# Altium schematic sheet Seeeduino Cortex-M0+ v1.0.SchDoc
size 545 x 376 mm; Origin: Eagle
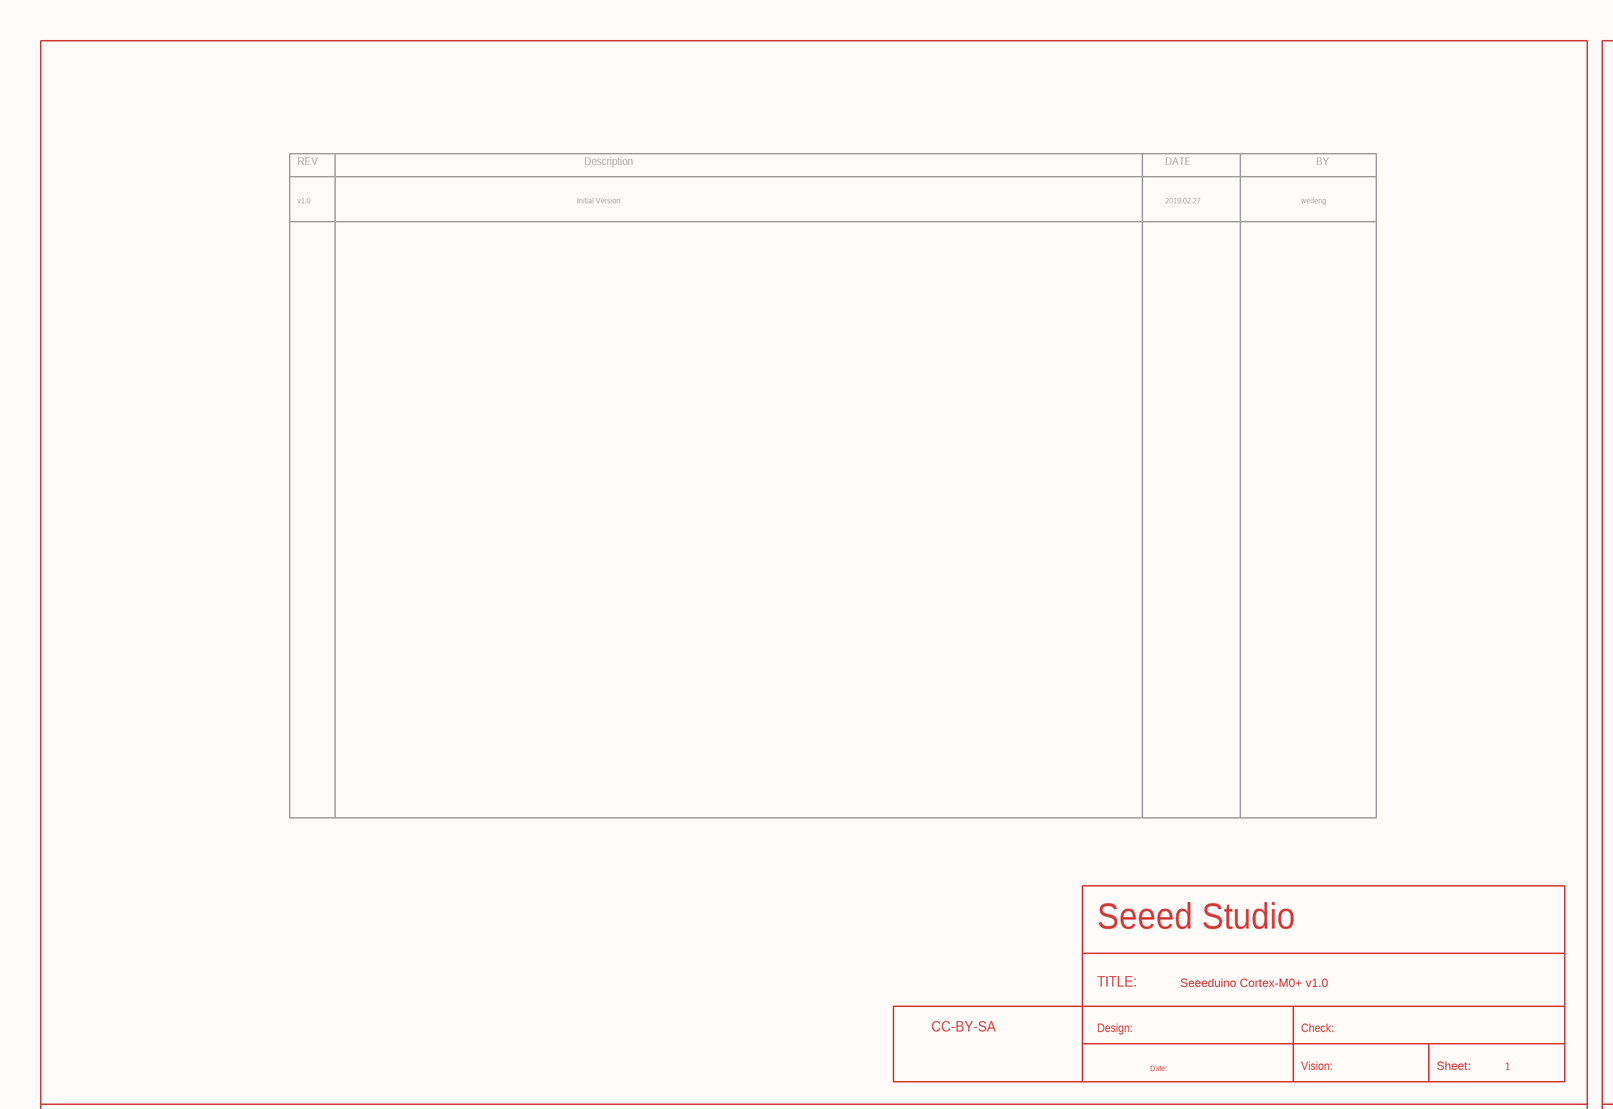
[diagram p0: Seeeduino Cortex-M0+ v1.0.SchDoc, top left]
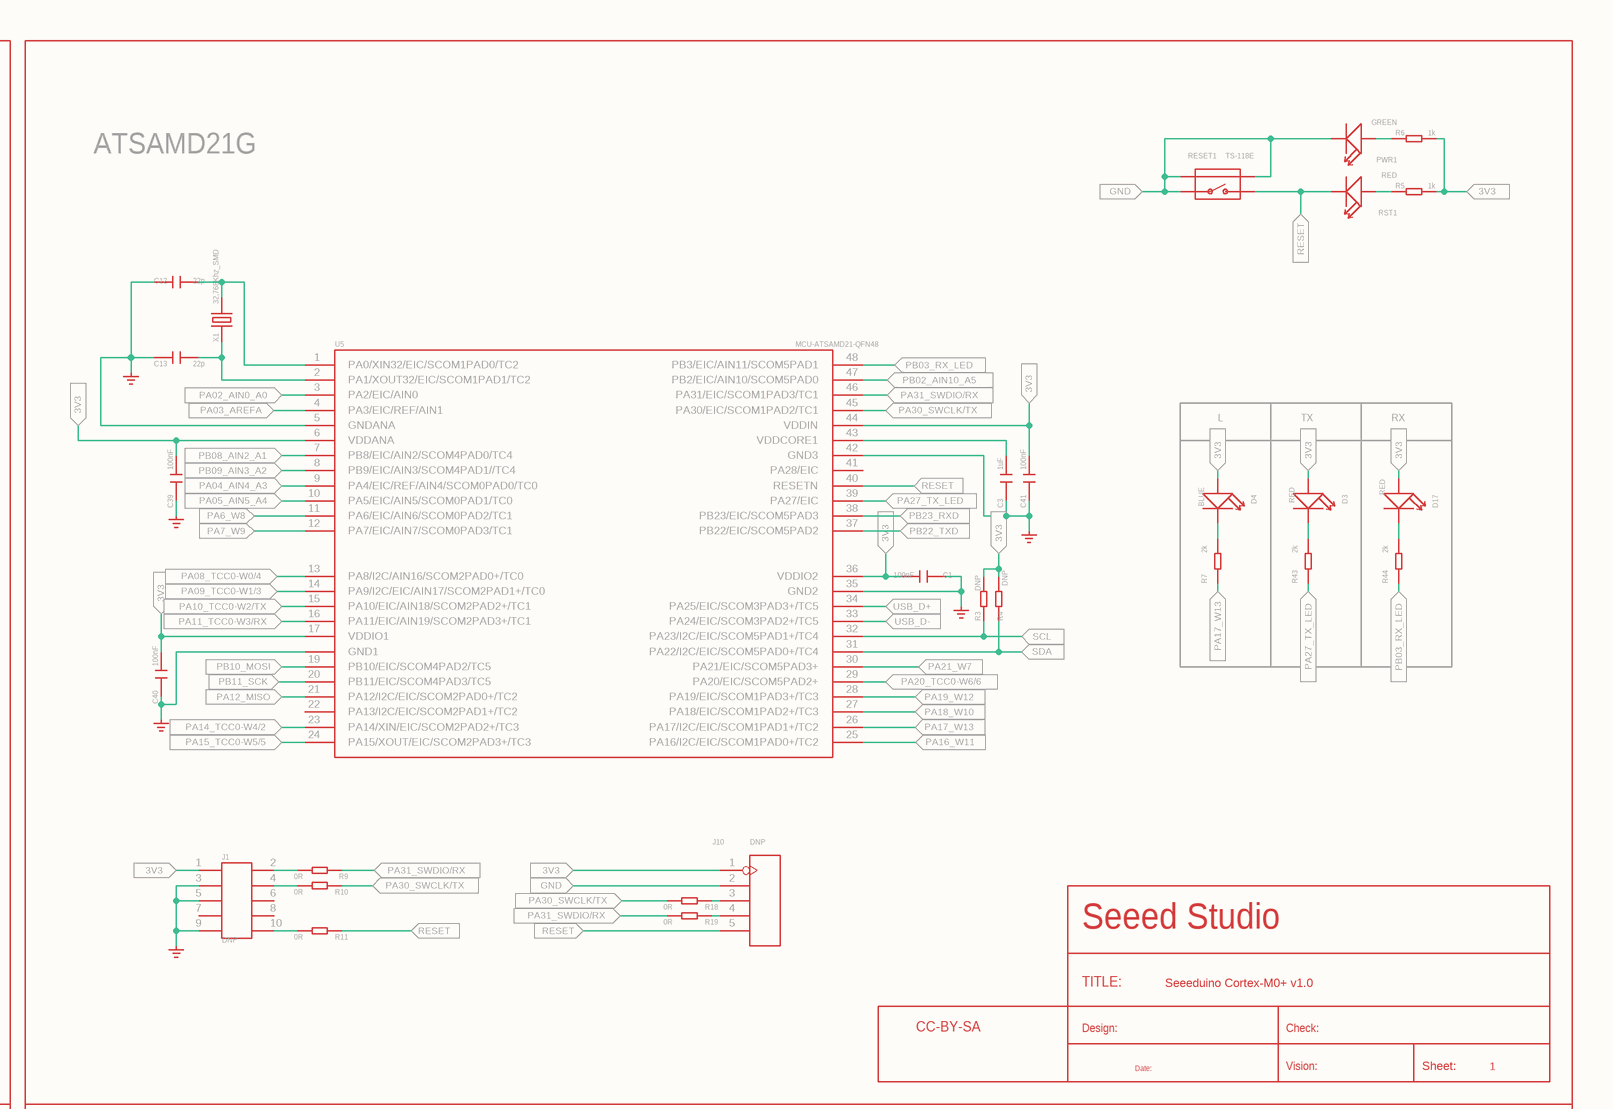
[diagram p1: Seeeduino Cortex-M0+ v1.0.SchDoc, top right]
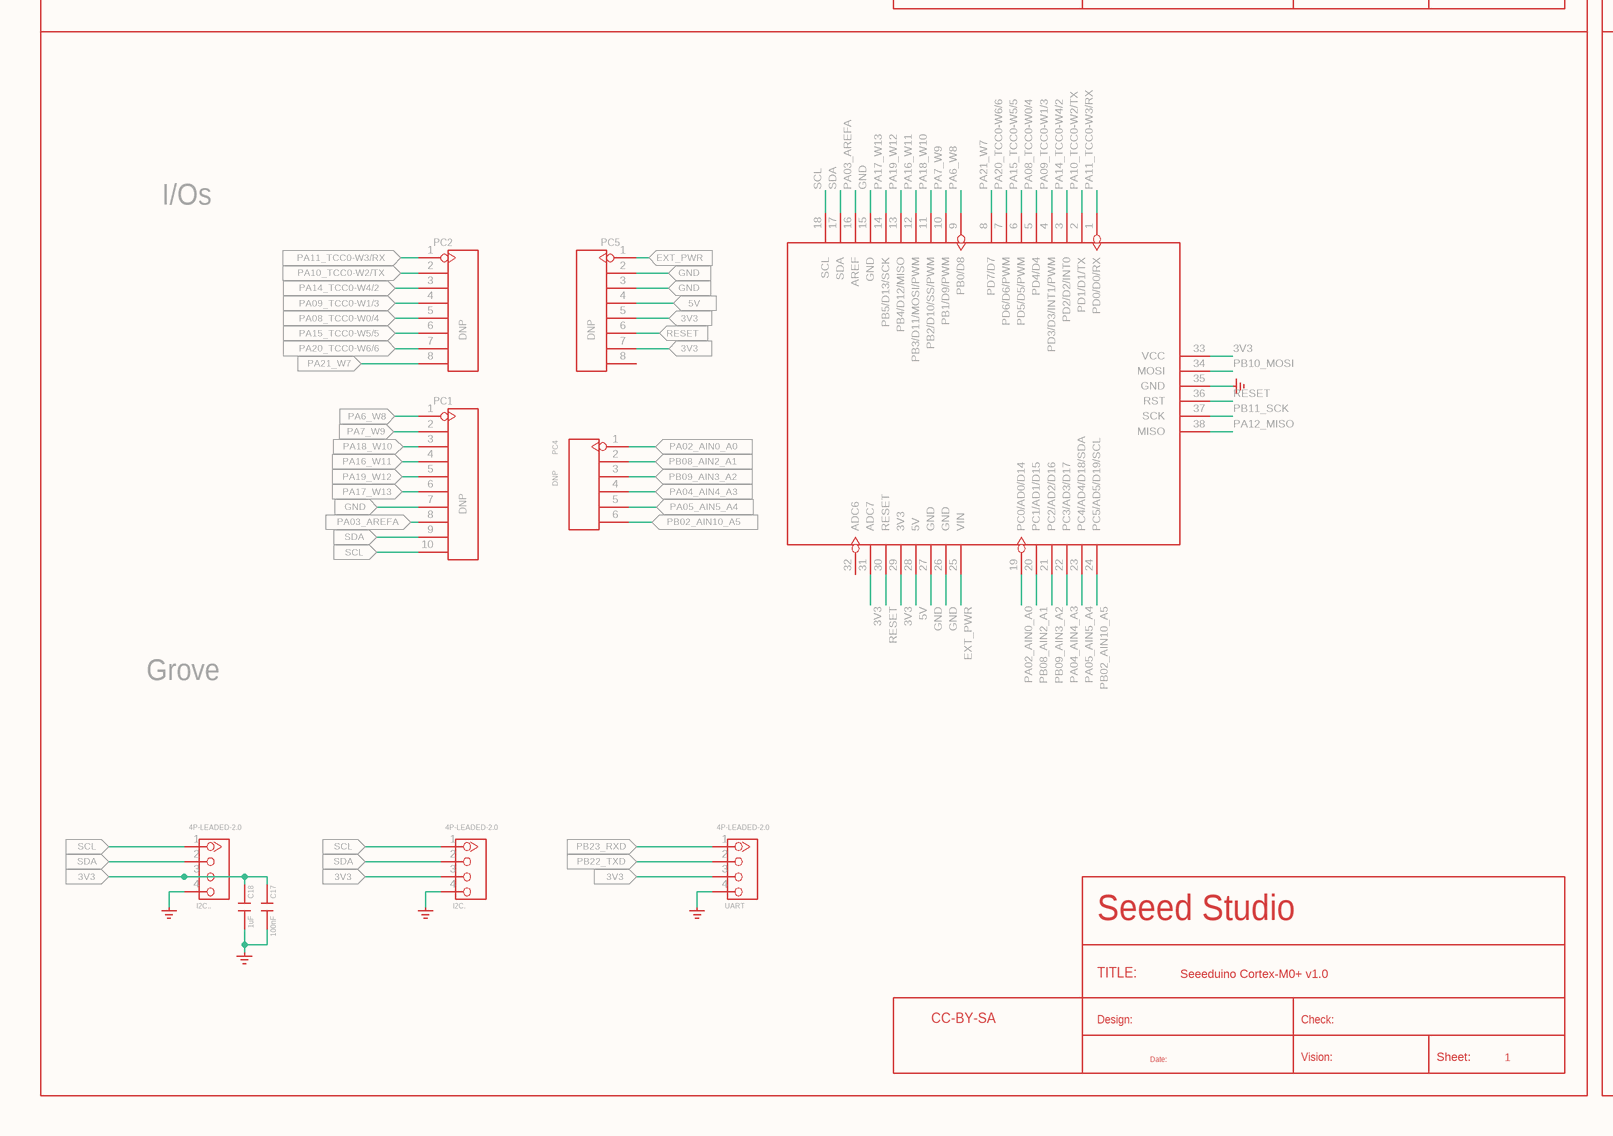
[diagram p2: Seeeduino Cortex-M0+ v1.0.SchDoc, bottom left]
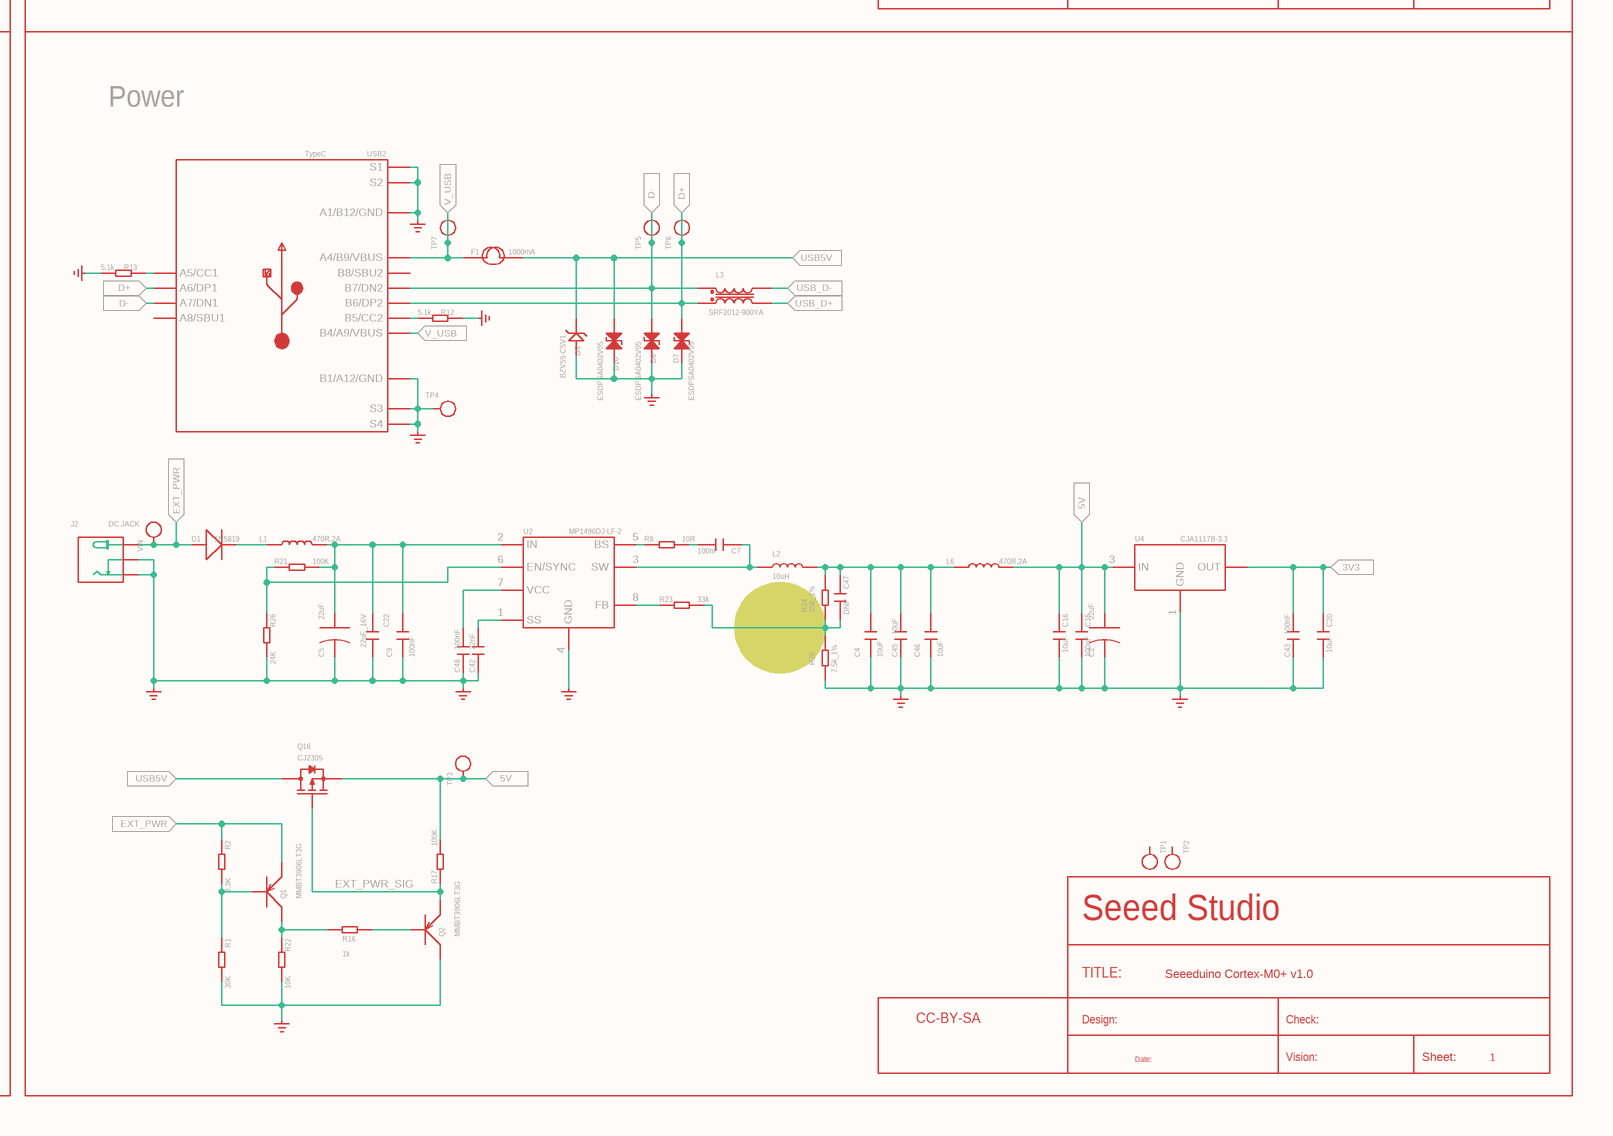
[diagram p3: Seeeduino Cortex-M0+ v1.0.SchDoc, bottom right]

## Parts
C1  100nF  [C0603]
C2  22uF  [ELECTRO-SMD-B-4.8MM]
C3  1uF  [C0603]
C4  10uF  [C0805]
C5  22uF  [ELECTRO-SMD-B-4.8MM]
C7  100nF  [C0603]
C9  100nF  [C0603]
C12  22p  [C0603]
C13  22p  [C0603]
C15  100nF  [C0603]
C16  10uF  [C0805]
C17  100nF  [C0603]
C18  1uF  [C0603]
C20  10uF  [C0805]
C22  22uF_16V  [C1206]
C39  100nF  [C0603]
C40  100nF  [C0603]
C41  100nF  [C0603]
C42  22nF  [C0603]
C43  100nF  [C0603]
C45  10uF  [C0805]
C46  10uF  [C0805]
C47  DNP  [C0603]
C48  100nF  [C0603]
D1  1N5819  [D2010]
D3  RED  [LED-0603]
D4  BLUE  [LED-0603]
D5  BZV55-C5V1  [SOD80C]
D6  ESDPSA0402V05  [ESD-0402]
D7  ESDPSA0402V05  [ESD-0402]
D10  ESDPSA0402V05  [ESD-0402]
D17  RED  [LED-0603]
F1  1000mA  [F1206]
I2C.  4P-LEADED-2.0  [4P-LEADED-2.0]
I2C..  4P-LEADED-2.0  [4P-LEADED-2.0]
J1  DNP  [H2X5-1.27]
J2  DC JACK  [DCJ3P-11.6X9.6X7.0MM]
J10  DNP  [H5-2.54]
L1  470R,2A  [L0805]
L2  10uH  [L5040S]
L3  SRF2012-900YA  [INT4-0.85-2X1.25X1.2MM]
L6  470R,2A  [L0805]
PC1  DNP  [10P-2.54]
PC2  DNP  [8P-2.54]
PC4  DNP  [6P-2.54-65/35MIL]
PC5  DNP  [8P-2.54]
PWR1  GREEN  [LED-0603]
Q1  MMBT3906LT3G  [SOT23]
Q2  MMBT3906LT3G  [SOT23]
Q16  CJ2305  [SOT23]
R1  30K  [R0603]
R2  3.3K  [R0603]
R3  DNP  [R0603]
R4  DNP  [R0603]
R5  1k  [R0603]
R6  1k  [R0603]
R7  2k  [R0603]
R8  10R  [R0603]
R9  0R  [R0603]
R10  0R  [R0603]
R11  0R  [R0603]
R12  5.1k  [R0603]
R13  5.1k  [R0603]
R16  1k  [R0603]
R17  100K  [R0603]
R18  0R  [R0603]
R19  0R  [R0603]
R20  7.5k_1%  [R0603]
R21  100K  [R0603]
R22  10K  [R0603]
R23  33k  [R0603]
R24  39k_1%  [R0603]
R26  24K  [R0603]
R43  2k  [R0603]
R44  2k  [R0603]
RESET1  TS-118E  [4P-SMD-7X3.5X3.5H]
RST1  RED  [LED-0603]
TP1  TEST-POINT'4545'  [TP-D45MIL]  (value not drawn)
TP2  TEST-POINT'4545'  [TP-D45MIL]  (value not drawn)
TP3  TEST-POINT'4545'  [TP-D45MIL]  (value not drawn)
TP4  TEST-POINT'4545'  [TP-D45MIL]  (value not drawn)
TP5  TEST-POINT'4545'  [TP-D45MIL]  (value not drawn)
TP6  TEST-POINT'4545'  [TP-D45MIL]  (value not drawn)
TP7  TEST-POINT'4545'  [TP-D45MIL]  (value not drawn)
U2  MP1496DJ-LF-2  [TSOT23-8]
U3  ARDUINO-38P  [ARDUINO-38P]  (value not drawn)
U4  CJA1117B-3.3  [SOT-89]
U5  MCU-ATSAMD21-QFN48  [QFN48-7X7]
U$1  DRAWING_NAME: Seeeduino Cortex-M0+ v1.0  SHEET: 1  Sheet: Sheet:  SeeedStudio: Seeed Studio  TITLE: TITLE:  Design: Design:  Check: Check:  Vision: Vision:  Date: Date:  [SEEEDSTUDIO-PCB-FRAME]  (hidden comment: SEEEDSTUDIO-OPEN-SCH-FRAME)
U$2  GND_POWER  (value not drawn)
U$4  GND_POWER  (value not drawn)
U$6  DRAWING_NAME: Seeeduino Cortex-M0+ v1.0  SHEET: 1  Sheet: Sheet:  SeeedStudio: Seeed Studio  TITLE: TITLE:  Design: Design:  Check: Check:  Vision: Vision:  Date: Date:  [SEEEDSTUDIO-PCB-FRAME]  (hidden comment: SEEEDSTUDIO-OPEN-SCH-FRAME)
U$7  GND_POWER  (value not drawn)
U$8  DRAWING_NAME: Seeeduino Cortex-M0+ v1.0  SHEET: 1  Sheet: Sheet:  SeeedStudio: Seeed Studio  TITLE: TITLE:  Design: Design:  Check: Check:  Vision: Vision:  Date: Date:  [SEEEDSTUDIO-PCB-FRAME]  (hidden comment: SEEEDSTUDIO-OPEN-SCH-FRAME)
U$9  GND_POWER  (value not drawn)
U$10  GND_POWER  (value not drawn)
U$11  GND_POWER  (value not drawn)
U$12  GND_POWER  (value not drawn)
U$13  GND_POWER  (value not drawn)
U$14  GND_POWER  (value not drawn)
U$15  SEEDSTUDIO-SCH-MODLIST  (value not drawn)
U$16  GND_POWER  (value not drawn)
U$17  GND_POWER  (value not drawn)
U$18  GND_POWER  (value not drawn)
U$20  GND_POWER  (value not drawn)
U$21  GND_POWER  (value not drawn)
U$22  GND_POWER  (value not drawn)
U$23  DRAWING_NAME: Seeeduino Cortex-M0+ v1.0  SHEET: 1  Sheet: Sheet:  SeeedStudio: Seeed Studio  TITLE: TITLE:  Design: Design:  Check: Check:  Vision: Vision:  Date: Date:  [SEEEDSTUDIO-PCB-FRAME]  (hidden comment: SEEEDSTUDIO-OPEN-SCH-FRAME)
U$24  GND_POWER  (value not drawn)
U$25  GND_POWER  (value not drawn)
U$31  GND_POWER  (value not drawn)
U$32  GND_POWER  (value not drawn)
U$42  GND_POWER  (value not drawn)
U$49  GND_POWER  (value not drawn)
U$76  GND_POWER  (value not drawn)
UART  4P-LEADED-2.0  [4P-LEADED-2.0]
USB2  TypeC  [USB2.0-TYPE-C]
VIN  TEST-POINT'4545'  [TP-D45MIL]  (value not drawn)
X1  32,768Khz_SMD  [X2-SMD-L2.0X1.2X0.55MM]

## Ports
3V3 (in), 5V (in), D+ (in), D- (in), EXT_PWR (in), GND (in), PA02_AIN0_A0 (in), PA03_AREFA (in), PA04_AIN4_A3 (in), PA05_AIN5_A4 (in), PA6_W8 (in), PA7_W9 (in), PA08_TCC0-W0/4 (in), PA09_TCC0-W1/3 (in), PA10_TCC0-W2/TX (in), PA11_TCC0-W3/RX (in), PA12_MISO (in), PA14_TCC0-W4/2 (in), PA15_TCC0-W5/5 (in), PA16_W11 (in), PA17_W13 (in), PA18_W10 (in), PA19_W12 (in), PA20_TCC0-W6/6 (in), PA21_W7 (in), PA27_TX_LED (in), PA30_SWCLK/TX (in), PA31_SWDIO/RX (in), PB02_AIN10_A5 (in), PB03_RX_LED (in), PB08_AIN2_A1 (in), PB09_AIN3_A2 (in), PB10_MOSI (in), PB11_SCK (in), PB22_TXD (in), PB23_RXD (in), RESET (in), SCL (in), SDA (in), USB5V (in), USB_D+ (in), USB_D- (in), V_USB (in)

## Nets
3V3: C1.2 C17.2 C18.2 C20.1 C39.2 C40.2 C41.2 C43.2 D3.+ D4.+ D17.+ I2C..3 I2C...3 J1.1 J10.1 PC5.5 PC5.7 R3.2 R4.1 R5.1 R6.1 U4.2_4(OUT) U5.6(VDDANA) U5.17(VDDIO1) U5.36(VDDIO2) U5.44(VDDIN) UART.3 ; port 3V3
3V3: U3.29(3V3) U3.31(ADC7) U3.33(VCC)  [a separate net that carries the same name]
5V: C2.+ C15.1 C16.1 L6.2 PC5.4 Q16.2(S) R17.2 TP3.T U4.3(IN) ; port 5V
5V: U3.28(5V)  [a separate net that carries the same name]
D+: D7.2 L3.4 TP6.T USB2.A6(A6/DP1) USB2.B6(B6/DP2) ; port D+
D-: D6.2 L3.1 TP5.T USB2.A7(A7/DN1) USB2.B7(B7/DN2) ; port D-
EXT_PWR: D1.+ J2.+ PC5.1 Q1.2(E) R2.1 VIN.T ; port EXT_PWR
EXT_PWR: U3.25(VIN)  [a separate net that carries the same name]
EXT_PWR_SIG: Q2.2(E) Q16.1(G) R17.1
GND: J10.2 PC1.7 PC5.2 PC5.3 PWR1.- RESET1.1 RESET1.S1 RESET1.S2 ; port GND
GND: U3.15(GND) U3.26(GND) U3.27(GND)  [a separate net that carries the same name]
PA02_AIN0_A0: PC4.1 U5.3(PA2/EIC/AIN0) ; port PA02_AIN0_A0
PA02_AIN0_A0: U3.19(PC0/AD0/D14)  [a separate net that carries the same name]
PA03_AREFA: PC1.8 U5.4(PA3/EIC/REF/AIN1) ; port PA03_AREFA
PA03_AREFA: U3.16(AREF)  [a separate net that carries the same name]
PA04_AIN4_A3: PC4.4 U5.9(PA4/EIC/REF/AIN4/SCOM0PAD0/TC0) ; port PA04_AIN4_A3
PA04_AIN4_A3: U3.22(PC3/AD3/D17)  [a separate net that carries the same name]
PA05_AIN5_A4: PC4.5 U5.10(PA5/EIC/AIN5/SCOM0PAD1/TC0) ; port PA05_AIN5_A4
PA05_AIN5_A4: U3.23(PC4/AD4/D18/SDA)  [a separate net that carries the same name]
PA6_W8: PC1.1 U5.11(PA6/EIC/AIN6/SCOM0PAD2/TC1) ; port PA6_W8
PA6_W8: U3.9(PB0/D8)  [a separate net that carries the same name]
PA7_W9: PC1.2 U5.12(PA7/EIC/AIN7/SCOM0PAD3/TC1) ; port PA7_W9
PA7_W9: U3.10(PB1/D9/PWM)  [a separate net that carries the same name]
PA08_TCC0-W0/4: PC2.5 U5.13(PA8/I2C/AIN16/SCOM2PAD0+/TC0) ; port PA08_TCC0-W0/4
PA08_TCC0-W0/4: U3.5(PD4/D4)  [a separate net that carries the same name]
PA09_TCC0-W1/3: PC2.4 U5.14(PA9/I2C/EIC/AIN17/SCOM2PAD1+/TC0) ; port PA09_TCC0-W1/3
PA09_TCC0-W1/3: U3.4(PD3/D3/INT1/PWM)  [a separate net that carries the same name]
PA10_TCC0-W2/TX: PC2.2 U5.15(PA10/EIC/AIN18/SCOM2PAD2+/TC1) ; port PA10_TCC0-W2/TX
PA10_TCC0-W2/TX: U3.2(PD1/D1/TX)  [a separate net that carries the same name]
PA11_TCC0-W3/RX: PC2.1 U5.16(PA11/EIC/AIN19/SCOM2PAD3+/TC1) ; port PA11_TCC0-W3/RX
PA11_TCC0-W3/RX: U3.1(PD0/D0/RX)  [a separate net that carries the same name]
PA12_MISO: U3.38(MISO)
PA12_MISO: U5.21(PA12/I2C/EIC/SCOM2PAD0+/TC2) ; port PA12_MISO  [a separate net that carries the same name]
PA14_TCC0-W4/2: PC2.3 U5.23(PA14/XIN/EIC/SCOM2PAD2+/TC3) ; port PA14_TCC0-W4/2
PA14_TCC0-W4/2: U3.3(PD2/D2/INT0)  [a separate net that carries the same name]
PA15_TCC0-W5/5: PC2.6 U5.24(PA15/XOUT/EIC/SCOM2PAD3+/TC3) ; port PA15_TCC0-W5/5
PA15_TCC0-W5/5: U3.6(PD5/D5/PWM)  [a separate net that carries the same name]
PA16_W11: PC1.4 U5.25(PA16/I2C/EIC/SCOM1PAD0+/TC2) ; port PA16_W11
PA16_W11: U3.12(PB3/D11/MOSI/PWM)  [a separate net that carries the same name]
PA17_W13: PC1.6 R7.1 U5.26(PA17/I2C/EIC/SCOM1PAD1+/TC2) ; port PA17_W13
PA17_W13: U3.14(PB5/D13/SCK)  [a separate net that carries the same name]
PA18_W10: PC1.3 U5.27(PA18/EIC/SCOM1PAD2+/TC3) ; port PA18_W10
PA18_W10: U3.11(PB2/D10/SS/PWM)  [a separate net that carries the same name]
PA19_W12: PC1.5 U5.28(PA19/EIC/SCOM1PAD3+/TC3) ; port PA19_W12
PA19_W12: U3.13(PB4/D12/MISO)  [a separate net that carries the same name]
PA20_TCC0-W6/6: PC2.7 U5.29(PA20/EIC/SCOM5PAD2+) ; port PA20_TCC0-W6/6
PA20_TCC0-W6/6: U3.7(PD6/D6/PWM)  [a separate net that carries the same name]
PA21_W7: PC2.8 U5.30(PA21/EIC/SCOM5PAD3+) ; port PA21_W7
PA21_W7: U3.8(PD7/D7)  [a separate net that carries the same name]
PA27_TX_LED: R43.1 U5.39(PA27/EIC) ; port PA27_TX_LED
PA30_SWCLK/TX: R10.1 R18.2 U5.45(PA30/EIC/SCOM1PAD2/TC1) ; port PA30_SWCLK/TX
PA31_SWDIO/RX: R9.1 R19.2 U5.46(PA31/EIC/SCOM1PAD3/TC1) ; port PA31_SWDIO/RX
PB02_AIN10_A5: PC4.6 U5.47(PB2/EIC/AIN10/SCOM5PAD0) ; port PB02_AIN10_A5
PB02_AIN10_A5: U3.24(PC5/AD5/D19/SCL)  [a separate net that carries the same name]
PB03_RX_LED: R44.1 U5.48(PB3/EIC/AIN11/SCOM5PAD1) ; port PB03_RX_LED
PB08_AIN2_A1: PC4.2 U5.7(PB8/EIC/AIN2/SCOM4PAD0/TC4) ; port PB08_AIN2_A1
PB08_AIN2_A1: U3.20(PC1/AD1/D15)  [a separate net that carries the same name]
PB09_AIN3_A2: PC4.3 U5.8(PB9/EIC/AIN3/SCOM4PAD1//TC4) ; port PB09_AIN3_A2
PB09_AIN3_A2: U3.21(PC2/AD2/D16)  [a separate net that carries the same name]
PB10_MOSI: U3.34(MOSI)
PB10_MOSI: U5.19(PB10/EIC/SCOM4PAD2/TC5) ; port PB10_MOSI  [a separate net that carries the same name]
PB11_SCK: U3.37(SCK)
PB11_SCK: U5.20(PB11/EIC/SCOM4PAD3/TC5) ; port PB11_SCK  [a separate net that carries the same name]
PB22_TXD: U5.37(PB22/EIC/SCOM5PAD2) UART.2 ; port PB22_TXD
PB23_RXD: U5.38(PB23/EIC/SCOM5PAD3) UART.1 ; port PB23_RXD
RESET: J10.5 PC5.6 R11.1 RESET1.2 RST1.- U5.40(RESETN) ; port RESET
RESET: U3.30(RESET) U3.36(RST)  [a separate net that carries the same name]
SCL: I2C..1 I2C...1 PC1.10 R3.1 U5.32(PA23/I2C/EIC/SCOM5PAD1+/TC4) ; port SCL
SCL: U3.18(SCL)  [a separate net that carries the same name]
SDA: I2C..2 I2C...2 PC1.9 R4.2 U5.31(PA22/I2C/EIC/SCOM5PAD0+/TC4) ; port SDA
SDA: U3.17(SDA)  [a separate net that carries the same name]
USB5V: D5.2(-) D10.2 F1.2 Q16.3(D) ; port USB5V
USB_D+: L3.3 U5.34(PA25/EIC/SCOM3PAD3+/TC5) ; port USB_D+
USB_D-: L3.2 U5.33(PA24/EIC/SCOM3PAD2+/TC5) ; port USB_D-
V_USB: F1.1 TP7.T USB2.A4_B9(A4/B9/VBUS) USB2.B4_A9(B4/A9/VBUS) ; port V_USB
NetC1_1: C1.1 U5.35(GND2) U$12.?1(GND)
NetC2_-: C2.- C4.1 C15.2 C16.2 C20.2 C43.1 C45.1 C46.1 R20.1 U4.1(GND) U$18.?1(GND) U$32.?1(GND)
NetC3_1: C3.1 C41.1 U5.42(GND3) U$25.?1(GND)
NetC3_2: C3.2 U5.43(VDDCORE1)
NetC4_2: C4.2 C45.2 C46.2 C47.1 L2.2 L6.1 R24.1
NetC5_+: C5.+ C9.2 C22.1 L1.2 R21.2 U2.2(IN)
NetC5_-: C5.- C9.1 C22.2 C42.1 C48.1 J2.- J2.CDN R26.2 U$7.?1(GND) U$21.?1(GND)
NetC7_1: C7.1 L2.1 U2.3(SW)
NetC7_2: C7.2 R8.2
NetC12_1: C12.1 U5.1(PA0/XIN32/EIC/SCOM1PAD0/TC2) X1.2
NetC12_2: C12.2 C13.2 U5.5(GNDANA) U$10.?1(GND)
NetC13_1: C13.1 U5.2(PA1/XOUT32/EIC/SCOM1PAD1/TC2) X1.1
NetC17_1: C17.1 C18.1 U$16.?1(GND)
NetC39_1: C39.1 U$22.?1(GND)
NetC40_1: C40.1 U5.18_PAD(GND1) U$24.?1(GND)
NetC42_2: C42.2 U2.1(SS)
NetC47_2: C47.2 R20.2 R23.2 R24.2
NetC48_2: C48.2 U2.7(VCC)
NetD1_-: D1.- L1.1
NetD3_-: D3.- R43.2
NetD4_-: D4.- R7.2
NetD5_1: D5.1(+) D6.1 D7.1 D10.1 U$20.?1(GND)
NetD17_-: D17.- R44.2
NetI2C.._4: I2C...4 U$14.?1(GND)
NetI2C._4: I2C..4 U$13.?1(GND)
NetJ1_2: J1.2 R9.2
NetJ1_3: J1.3 J1.5 J1.9 U$17.?1(GND)
NetJ1_4: J1.4 R10.2
NetJ1_10: J1.10 R11.2
NetJ10_3: J10.3 R18.1
NetJ10_4: J10.4 R19.1
NetPWR1_+: PWR1.+ R6.2
NetQ1_1: Q1.1(B) R1.1 R2.2
NetQ1_3: Q1.3(C) R16.1 R22.1
NetQ2_1: Q2.1(B) R16.2
NetQ2_3: Q2.3(C) R1.2 R22.2 U$76.?1(GND)
NetR5_2: R5.2 RST1.+
NetR8_1: R8.1 U2.5(BS)
NetR12_1: R12.1 U$42.?1(GND)
NetR12_2: R12.2 USB2.B5(B5/CC2)
NetR13_1: R13.1 USB2.A5(A5/CC1)
NetR13_2: R13.2 U$49.?1(GND)
NetR21_1: R21.1 R26.1 U2.6(EN/SYNC)
NetR23_1: R23.1 U2.8(FB)
NetTP4_T: TP4.T U$4.?1(GND) USB2.B1_A12(B1/A12/GND) USB2.S3 USB2.S4
NetU2_4: U2.4(GND) U$31.?1(GND)
NetU3_35: U3.35(GND) U$11.?1(GND)
NetU$2_?1: U$2.?1(GND) USB2.A1_B12(A1/B12/GND) USB2.S1_S5(S1) USB2.S2_S6(S2)
NetU$9_?1: U$9.?1(GND) UART.4

Not connected (* = marked no-connect by the designer): J1 6 7 8; PC5 8; TP1 T; TP2 T; U3 32(ADC6); U5 22(PA13/I2C/EIC/SCOM2PAD1+/TC2) 41(PA28/EIC); USB2 A8(A8/SBU1) B8(B8/SBU2)

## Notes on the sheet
- (near U$15) v1.0
- Initial Version
- 2019.02.27
- weifeng
- ATSAMD21G
- L
- TX
- RX
- (near USB2) Power
- I/Os
- short route
- Grove

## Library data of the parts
C1 C3 C9 C12 C13 C17 C18 C39-C41 = CAP-0603: Ceramic Capacitors; GateName_1: C; DeviceName: -0603; DeviceSetName: CAP
C2 C5 = CAP-POLAR-ELECTRO-B: Electrolytic Capacitors,Tantalum Capacitors and Super Capacitors; GateName_1: C
C4 C46 = CAP-0805: Ceramic Capacitors; GateName_1: C; DeviceName: -0805; DeviceSetName: CAP
C7 C15 C42 C43 C47 C48 = C*-0603: Ceramic Capacitors; GateName_1: C; SymbolName_1: C@1; DeviceName: -0603; DeviceSetName: C*
C16 C20 C45 = C*-0805: Ceramic Capacitors; GateName_1: C; SymbolName_1: C@1; DeviceName: -0805; DeviceSetName: C*
C22 = CAP-1206: Ceramic Capacitors; GateName_1: C; DeviceName: -1206; DeviceSetName: CAP
D1 = D*'DO-214AC': GateName_1: D; SymbolName_1: DIODE; DeviceSetName: D*
D3 D4 D17 PWR1 RST1 = LED'0603': GateName_1: LED; DeviceName: '0603'
D5 = DIODE-BZV55: Low-power voltage regulator diodes in small hermetically sealed glass SOD80C Surface-Mounted Device (SMD) packages. The diodes are available in the normalized E24 ï‚±2 % (BZV55-B) and approximately ï‚±5 % (BZV55-C) tolerance range. The series consists of 37 types with nominal working voltages from 2.4 V to 75 V.; GateName_1: D
D6 D7 D10 = D-ESD-2P-DOUBLE-0402: GateName_1: G$1; DeviceName: -0402
F1 = FUSE'1206': GateName_1: F; SymbolName_1: FUSE; DeviceName: '1206'
I2C. I2C.. UART = TWIG-2.0-LEADED: GateName_1: G$1; SymbolName_1: TWIG_2.0
J1 = HEADER-2X5P-1.27: GateName_1: G$1
J2 = POWER-JACK-DC'DC-044': 3P-L11.6*W9.6*H7.0MM:320120002;3P-L14.2*W11.0*H9.0MM:320120003
J10 = HEADER-5P-2.54: GateName_1: G$1; DeviceName: -2.54
L1 L6 = L*'0805': GateName_1: L; DeviceName: '0805'; DeviceSetName: L*
L2 = INDUCTOR/FERRITE-BEAD5040S: GateName_1: L; DeviceName: 5040S
L3 = INDUCTOR-COMMON-MODE-SRF2012-900YA: GateName_1: G$1
PC1 = HEADER-10P-2.54: GateName_1: J; SymbolName_1: 10P; DeviceName: -2.54
PC2 PC5 = HEADER-8P-2.54: GateName_1: J; SymbolName_1: CK_1X8; DeviceName: -2.54
PC4 = HEADER-6P-65/35MIL: GateName_1: J; SymbolName_1: CK_1X6
Q1 Q2 = TRANSISTOR-PNP*-SOT23: PNP audion; GateName_1: G$1; DeviceName: -SOT23
Q16 = MOSFET-P'SI2323CDS/SI2305DS<BR>': GateName_1: MOS; SymbolName_1: P-MOS
R1 R2 R8 R16 R17 R20-R24 R26 = R*-0603: GateName_1: R; DeviceName: -0603; DeviceSetName: R*
R3-R7 R9-R13 R18 R19 R43 R44 = RES-0603: GateName_1: R; SymbolName_1: RES-ARRAY; DeviceName: -0603; DeviceSetName: RES
RESET1 = BUTTON-4P-REINFORCE'TS-1188E': TS-1188E  http://www.best-dz.com/?thread-374-2.html; GateName_1: SW; SymbolName_1: BUTTON-4P-SMD
TP1-TP7 VIN = TEST-POINT'4545': PARTNO: DNP; GateName_1: TP; DeviceName: '4545'
U2 = MP1496DJ: High-Efficiency,2Aï¼Œ16V,500kHz Synchronous,Step-Down Converter   http://html.alldatasheetcn.com/html-pdf/551584/MPS/MP1496DJ/55/1/MP1496DJ.html; GateName_1: G$1; SymbolName_1: MP1496
U3 = ARDUINO-38P: GateName_1: SEEEDUINO
U4 = PMIC-CJ*1117'SOT89': Low Drop Fixed And Adjustable Positive Voltage Regulators http://www.datasheetcatalog.org/datasheet/SGSThomsonMicroelectronics/mXuqtqv.pdf; GateName_1: G$1
U5 = MCU-ATSAMD21-QFN48: Atmel D21 32bit ARM Cortex-M0  microcontroller - 48 PIN TQFP 256KB flash memory + 32KB SRAM; GateName_1: SAMD; DeviceName: -QFN48
U$1 U$6 U$8 U$23 = SEEEDSTUDIO-OPEN-SCH-FRAME: GateName_1: G$1
U$2 U$4 U$7 U$9-U$14 U$16-U$18 U$20-U$22 U$24 U$25 U$31 U$32 U$42 U$49 U$76 = GND_POWER: GateName_1: G$1
U$15 = SEEDSTUDIO-SCH-MODLIST: GateName_1: G$1
USB2 = USB2.0-TYPE-C: GateName_1: USB
X1 = CRYSTAL-2P'NX2012SA': GateName_1: X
